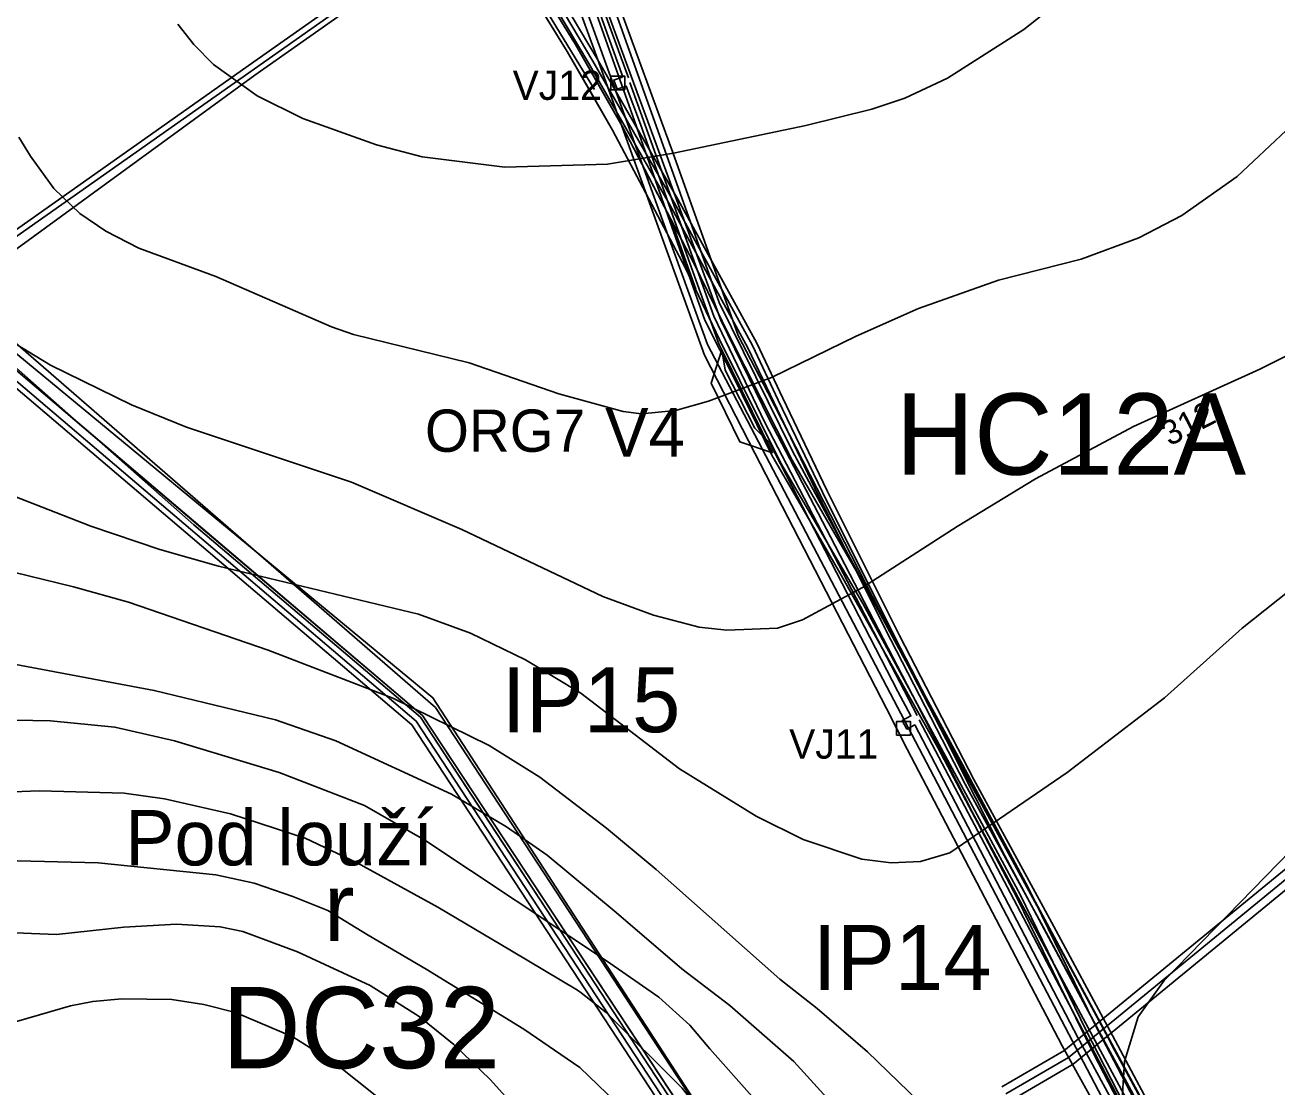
# Model space of a CAD drawing. Extents: x -1900516 to -575031, y -3809306 to -1157387.
# Drawn here: x -577737.9 to -577352.9, y -1159075.4 to -1158748.8 of the extents above; entities that cross this region are included whole.
import ezdxf

# ---------------------------------------------------------------- set-up
doc = ezdxf.new("R2010")
doc.units = 0
for name, color, linetype in [('01_MÍSTNÍ_NÁZVY', 7, 'Continuous'), ('01_PARCELY_NÁVRH_PC', 7, 'Continuous'), ('01_PARCELY_NÁVRH_ŽP', 7, 'Continuous'), ('01_PRVKY PRŮZKUMU', 7, 'Continuous'), ('01_PRVKY PSZ', 7, 'Continuous'), ('01_VRSTEVNICE', 7, 'Continuous'), ('02_KULTURY STAV', 7, 'Continuous'), ('03_PC_NÁVRH', 7, 'Continuous'), ('03_PC_OBJEKTY_NÁVRH', 7, 'Continuous'), ('03_PC_POPIS_NÁVRH', 7, 'Continuous'), ('04_ZPF_OP_ORGAN', 7, 'Continuous'), ('06_REVITALIZACE', 7, 'Continuous'), ('06_ÚSES_IP', 7, 'Continuous'), ('07_OCH_P A POPISY TI', 7, 'Continuous'), ('07_SDĚLOVACÍ', 7, 'Continuous'), ('07_VODOVOD', 7, 'Continuous')]:
    doc.layers.add(name, color=color, linetype=linetype)

msp = doc.modelspace()

# ---------------------------------------------------------------- linework, layer by layer
at = {"layer": '01_PARCELY_NÁVRH_PC'}
for points in [[(-577351.76, -1159160.35), (-577354.61, -1159155.38), (-577356.51, -1159151.86), (-577356.86, -1159151.18), (-577370.68, -1159126.55), (-577389.27, -1159092.33), (-577397.73, -1159076.44), (-577408.74, -1159056.24), (-577436.58, -1159004.27), (-577445.6, -1158986.42), (-577454.65, -1158968.56), (-577470.2, -1158938.32), (-577472.99, -1158933.04), (-577509.53, -1158861.87), (-577518.63, -1158844.3), (-577538.75, -1158787.99), (-577582.32, -1158668.78)], [(-577583.17, -1158700.75), (-577669.28, -1158761.41), (-577757.08, -1158823.28), (-577761.2, -1158827.86), (-577763.11, -1158834.28), (-577761.87, -1158840.85), (-577758.1, -1158845.78), (-577618.94, -1158964.02), (-577533.99, -1159093.64), (-577453.13, -1159217.05), (-577454.97, -1159225.17), (-577441.7, -1159217.16), (-577450.13, -1159215.24), (-577531.07, -1159091.72), (-577573.66, -1159026.72), (-577616.28, -1158961.68), (-577685.96, -1158902.49), (-577754.76, -1158841.86), (-577757.35, -1158838.39), (-577757.96, -1158834.51), (-577756.72, -1158830.19), (-577754.11, -1158827.49), (-577667.26, -1158764.27), (-577581.95, -1158704.17)], [(-577575.02, -1158706.36), (-577558.49, -1158752.55), (-577554.03, -1158764.77), (-577556.85, -1158765.79), (-577555.84, -1158768.61), (-577553.01, -1158767.59), (-577548.69, -1158779.36), (-577538.23, -1158808.96), (-577524.51, -1158846.88), (-577523.62, -1158848.73), (-577522.65, -1158854.98), (-577513.5, -1158872.76), (-577508.98, -1158877.19), (-577469.52, -1158953.79), (-577465.49, -1158961.25), (-577468.14, -1158962.67), (-577466.73, -1158965.31), (-577464.31, -1158964.03), (-577414.11, -1159060.16), (-577394.03, -1159097.19)]]:
    msp.add_lwpolyline(points, dxfattribs=at)
at = {"layer": '01_PARCELY_NÁVRH_ŽP'}
for points in [[(-577581.95, -1158704.17), (-577561.09, -1158761.47), (-577528.93, -1158850.38), (-577513.46, -1158880.5), (-577472.95, -1158959.01), (-577466.62, -1158971.48), (-577418.97, -1159062.74), (-577380.99, -1159131.08)], [(-577394.03, -1159097.19), (-577414.11, -1159060.16), (-577464.31, -1158964.02), (-577466.73, -1158965.31), (-577468.14, -1158962.67), (-577465.49, -1158961.25), (-577469.52, -1158953.79), (-577508.98, -1158877.19), (-577513.5, -1158872.76), (-577522.65, -1158854.98), (-577523.62, -1158848.73), (-577524.51, -1158846.88), (-577538.23, -1158808.96), (-577548.69, -1158779.36), (-577553.01, -1158767.59), (-577555.84, -1158768.61), (-577556.85, -1158765.79), (-577554.03, -1158764.77), (-577558.49, -1158752.55), (-577575.02, -1158706.36)]]:
    msp.add_lwpolyline(points, dxfattribs=at)
msp.add_lwpolyline([(-577611.67, -1158958.68), (-577751.04, -1158837.81), (-577757.34, -1158832.35), (-577757.96, -1158834.51), (-577757.35, -1158838.39), (-577754.76, -1158841.86), (-577685.96, -1158902.49), (-577616.28, -1158961.68), (-577594.97, -1158994.2), (-577573.66, -1159026.72), (-577531.07, -1159091.72), (-577450.13, -1159215.24), (-577441.7, -1159217.16), (-577445.54, -1159212.21)], close=True, dxfattribs=at)
at = {"layer": '01_PRVKY PRŮZKUMU'}
for p, q in [((-577571.21, -1158756.93), (-577582.84, -1158738.08)), ((-577580.08, -1158736.23), (-577568.65, -1158754.78)), ((-577568.65, -1158754.78), (-577561.45, -1158767.37)), ((-577564.26, -1158769.02), (-577571.21, -1158756.93)), ((-577557.3, -1158781.12), (-577564.26, -1158769.02)), ((-577561.45, -1158767.37), (-577554.25, -1158779.96)), ((-577546.08, -1158802.24), (-577557.3, -1158781.12)), ((-577554.25, -1158779.96), (-577543.28, -1158800.93)), ((-577543.28, -1158800.93), (-577539.28, -1158808.57)), ((-577534.87, -1158823.35), (-577546.08, -1158802.24)), ((-577531.67, -1158830.04), (-577539.28, -1158808.57)), ((-577531.67, -1158830.04), (-577534.87, -1158823.35))]:
    msp.add_line(p, q, dxfattribs=at)
at = {"layer": '01_PRVKY PSZ'}
for points in [[(-577557.73, -1158768.76), (-577553.51, -1158768.76), (-577553.51, -1158764.54), (-577557.73, -1158764.54)], [(-577469.87, -1158967.17), (-577465.64, -1158967.17), (-577465.64, -1158962.95), (-577469.87, -1158962.95)]]:
    msp.add_lwpolyline(points, close=True, dxfattribs=at)
at = {"layer": '01_VRSTEVNICE'}
for points in [[(-577159.9, -1158732.48), (-577156.09, -1158754.21), (-577154.68, -1158768.04), (-577153.97, -1158786.38), (-577154.25, -1158797.1), (-577155.38, -1158806.42), (-577158.34, -1158818.83), (-577164.84, -1158836.89), (-577172.74, -1158851), (-577180.36, -1158861.02), (-577185.15, -1158866.1), (-577204.77, -1158882.89), (-577248.65, -1158912.24), (-577284.34, -1158940.88), (-577302.68, -1158957.24), (-577329.21, -1158982.64), (-577387.62, -1159042.6), (-577395.61, -1159053.76)], [(-577413.72, -1158736.72), (-577430.8, -1158750.26), (-577454.22, -1158765.22), (-577467.34, -1158771.28), (-577477.5, -1158774.67), (-577497.81, -1158779.75), (-577538.45, -1158788.21), (-577558.77, -1158791.6), (-577590.37, -1158792.59), (-577615.77, -1158789.34), (-577629.88, -1158785.67), (-577652.45, -1158777.63), (-577666.56, -1158770.58), (-577679.96, -1158760.98), (-577686.03, -1158754.78), (-577690.97, -1158748.57)], [(-577350.09, -1158781.3), (-577365.19, -1158795.41), (-577382.12, -1158807.4), (-577395.38, -1158814.32), (-577413.16, -1158820.81), (-577438.56, -1158827.3), (-577463.11, -1158836.04), (-577482.29, -1158844.51), (-577508.4, -1158857.21), (-577527.73, -1158864.54), (-577537.89, -1158867.37), (-577548.33, -1158868.35), (-577553.97, -1158867.65), (-577573.72, -1158862.29), (-577601.38, -1158852.69), (-577636.93, -1158843.95), (-577643.7, -1158841.69), (-577679.26, -1158826.17), (-577702.96, -1158817.42), (-577713.12, -1158812.2), (-577721.02, -1158806.84), (-577729.07, -1158799.08), (-577736.26, -1158789.2), (-577739.79, -1158783.28)], [(-577333.86, -1158842.53), (-577358.13, -1158854.67), (-577397.07, -1158872.3), (-577427.13, -1158888.39), (-577451.25, -1158903.06), (-577480.32, -1158921.83), (-577498.8, -1158931.71), (-577506.56, -1158934.25), (-577522.08, -1158934.95), (-577530.55, -1158933.96), (-577544.66, -1158930.29), (-577560.18, -1158924.51), (-577603.63, -1158903.91), (-577637.5, -1158889.38), (-577688.29, -1158872.45), (-577705.22, -1158865.67), (-577730.05, -1158853.4), (-577754.04, -1158838.87)], [(-577345.72, -1158920), (-577363.64, -1158934.25), (-577387.48, -1158955.69), (-577417.39, -1158978.69), (-577453.51, -1159003.38), (-577462.54, -1159006.06), (-577471.57, -1159006.49), (-577480.6, -1159005.36), (-577498.66, -1158999.29), (-577513.05, -1158992.09), (-577536.61, -1158977.56), (-577566.95, -1158954.28), (-577584.02, -1158943.98), (-577600.95, -1158935.8), (-577616.9, -1158930.01), (-577678.41, -1158915.2), (-577696.47, -1158910.12), (-577717.64, -1158902.92), (-577754.32, -1158888.67)], [(-577755.45, -1158913.65), (-577723, -1158921.55), (-577706.07, -1158926.34), (-577663.18, -1158941.02), (-577624.8, -1158955.83), (-577595.17, -1158970.36), (-577579.65, -1158980.1), (-577559.05, -1158995.76), (-577543.81, -1159008.46), (-577505.83, -1159042.26)], [(-577755.45, -1158913.65), (-577723, -1158921.55), (-577706.07, -1158926.34), (-577663.18, -1158941.02), (-577624.8, -1158955.83), (-577595.17, -1158970.36), (-577579.65, -1158980.1), (-577559.05, -1158995.76), (-577543.81, -1159008.46), (-577505.83, -1159042.26)], [(-577773.51, -1158939.32), (-577698.17, -1158953.43), (-577660.92, -1158962.46), (-577642.29, -1158968.95), (-577606.74, -1158985.32), (-577589.81, -1158995.34), (-577577.39, -1159004.09), (-577556.08, -1159021.72), (-577535.9, -1159039.02)], [(-577773.51, -1158939.32), (-577698.17, -1158953.43), (-577660.92, -1158962.46), (-577642.29, -1158968.95), (-577606.74, -1158985.32), (-577589.81, -1158995.34), (-577577.39, -1159004.09), (-577556.08, -1159021.72), (-577535.9, -1159039.02)], [(-577768.15, -1158962.04), (-577730.05, -1158962.75), (-577710.3, -1158964.72), (-577691.96, -1158968.95), (-577659.79, -1158978.69), (-577633.55, -1158988.85), (-577614.92, -1158999.43), (-577559.15, -1159036.54)], [(-577768.15, -1158962.04), (-577730.05, -1158962.75), (-577710.3, -1158964.72), (-577691.96, -1158968.95), (-577659.79, -1158978.69), (-577633.55, -1158988.85), (-577614.92, -1158999.43), (-577559.15, -1159036.54)], [(-577632.38, -1159028.65), (-577644.83, -1159021.08), (-577655.56, -1159016.78), (-577667.41, -1159012.69), (-577679.26, -1159010.15), (-577715.38, -1159006.49), (-577761.09, -1159005.36), (-577821.76, -1158998.87), (-577833.61, -1158994.77), (-577852.24, -1158983.2), (-577856.33, -1158982.92), (-577860.04, -1158983.83), (-577862.96, -1158986.87), (-577870.3, -1158996.04), (-577875.01, -1159003.03)], [(-577752.63, -1158985.04), (-577733.44, -1158984.33), (-577707.48, -1158985.04), (-577695.06, -1158986.73), (-577674.74, -1158991.39), (-577651.75, -1158998.86), (-577635.8, -1159006.48), (-577610.97, -1159020.03), (-577588.27, -1159033.46)], [(-577752.63, -1158985.04), (-577733.44, -1158984.33), (-577707.48, -1158985.04), (-577695.06, -1158986.73), (-577674.74, -1158991.39), (-577651.75, -1158998.86), (-577635.8, -1159006.48), (-577610.97, -1159020.03), (-577588.27, -1159033.46)], [(-577528.87, -1159360.3), (-577549.85, -1159284.52), (-577556.84, -1159251.8), (-577559.63, -1159235.02), (-577560.61, -1159218.25), (-577558.52, -1159164.55), (-577559.07, -1159150.57), (-577561.59, -1159133.79), (-577565.51, -1159118.41), (-577569.98, -1159106.39), (-577574.87, -1159097.44), (-577583.68, -1159085.42), (-577594.87, -1159073.11), (-577606.05, -1159062.35), (-577616.68, -1159053.68), (-577631.78, -1159044.17), (-577654.15, -1159033.82), (-577670.93, -1159027.53), (-577677.92, -1159026.13), (-577691.34, -1159025.29), (-577707.56, -1159026.27), (-577728.26, -1159028.51), (-577746.16, -1159027.81)], [(-577632.38, -1159028.65), (-577614.58, -1159039.14), (-577584.52, -1159057.59), (-577567.32, -1159069.34), (-577556.14, -1159080.1), (-577548.45, -1159089.05), (-577541.46, -1159098.7), (-577535.1, -1159108.52), (-577532.65, -1159114.5), (-577528.73, -1159127.64), (-577526.64, -1159141.06), (-577526.64, -1159153.65), (-577528.03, -1159170.43), (-577537.12, -1159216.57), (-577537.78, -1159230.12), (-577536.98, -1159237.54), (-577531.95, -1159266.9), (-577523.28, -1159292.07), (-577506.36, -1159334.02), (-577493.5, -1159373.17)], [(-577588.27, -1159033.46), (-577568.02, -1159045.57), (-577566.91, -1159046.41), (-577559.21, -1159052.42), (-577535.86, -1159075.77), (-577526.78, -1159087.23), (-577515.45, -1159105.83), (-577506.22, -1159127.92), (-577502.59, -1159143.02), (-577501.61, -1159159.8), (-577504.96, -1159191.68), (-577505.61, -1159217.18), (-577505.1, -1159233.35), (-577503.7, -1159252.64), (-577502.03, -1159262.71), (-577497.69, -1159279.49), (-577488.74, -1159301.3), (-577455.47, -1159363.38)], [(-577513.49, -1159079.26), (-577527.33, -1159063.6), (-577533.52, -1159056.37), (-577542.99, -1159047.8), (-577559.15, -1159036.54)], [(-577535.9, -1159039.02), (-577521.14, -1159050.35), (-577501.47, -1159067.52), (-577481.89, -1159089.05)], [(-577505.83, -1159042.26), (-577494.34, -1159051.2), (-577478.82, -1159064.58), (-577450.43, -1159091.99), (-577436.31, -1159104.43), (-577425.96, -1159111), (-577420.09, -1159112.26), (-577415.96, -1159112.31), (-577412.96, -1159111.56), (-577411, -1159110.58), (-577406.66, -1159107.26), (-577404.71, -1159104.71), (-577401.78, -1159099.12), (-577399.82, -1159067.52), (-577395.61, -1159053.76)], [(-577746.99, -1159057.03), (-577723.92, -1159050.46), (-577717.07, -1159049.06), (-577708.12, -1159048.22), (-577692.74, -1159048.5), (-577682.96, -1159050.04), (-577673.17, -1159052.42), (-577655.55, -1159059.97), (-577641.85, -1159068.64), (-577629.68, -1159078.28), (-577614.72, -1159093.25), (-577604.66, -1159106.11), (-577595.99, -1159121.77), (-577592.35, -1159133.52), (-577590.67, -1159147.22), (-577590.26, -1159166.79), (-577590.67, -1159196.99), (-577589, -1159217.13), (-577584.8, -1159235.02), (-577575.85, -1159264.11), (-577564.95, -1159304.38), (-577557.12, -1159340.17)]]:
    msp.add_lwpolyline(points, dxfattribs=at)
at = {"layer": '02_KULTURY STAV'}
for points in [[(-577594.48, -1158719.22), (-577571.21, -1158756.93), (-577557.3, -1158781.12), (-577534.87, -1158823.35), (-577524.3, -1158845.5), (-577505.5, -1158883.53), (-577480.29, -1158926.68), (-577452.77, -1158977.4), (-577431.83, -1159016.39), (-577411.67, -1159057.8), (-577388.29, -1159103.32), (-577365.57, -1159143.24), (-577356.66, -1159160.73), (-577357.02, -1159165.97), (-577359.5, -1159169.84), (-577371.82, -1159178.25), (-577420.8, -1159207.62), (-577527.72, -1159271.03), (-577597.7, -1159313.36), (-577671.8, -1159358.28)], [(-577671.8, -1159358.28), (-577597.7, -1159313.36), (-577527.72, -1159271.03), (-577420.8, -1159207.62), (-577371.82, -1159178.25), (-577359.5, -1159169.84), (-577357.02, -1159165.97), (-577356.66, -1159160.73), (-577365.57, -1159143.24), (-577388.29, -1159103.32), (-577411.67, -1159057.8), (-577431.83, -1159016.39), (-577452.77, -1158977.4), (-577480.29, -1158926.68), (-577505.5, -1158883.53), (-577524.3, -1158845.5), (-577534.87, -1158823.35), (-577557.3, -1158781.12), (-577571.21, -1158756.93), (-577594.48, -1158719.22)], [(-577671.8, -1159358.28), (-577597.7, -1159313.36), (-577527.72, -1159271.03), (-577420.8, -1159207.62), (-577371.82, -1159178.25), (-577359.5, -1159169.84), (-577357.02, -1159165.97), (-577356.66, -1159160.73), (-577365.57, -1159143.24), (-577388.29, -1159103.32), (-577411.67, -1159057.8), (-577431.83, -1159016.39), (-577452.77, -1158977.4), (-577480.29, -1158926.68), (-577505.5, -1158883.53), (-577524.3, -1158845.5), (-577534.87, -1158823.35), (-577557.3, -1158781.12), (-577571.21, -1158756.93), (-577594.48, -1158719.22)], [(-577343.83, -1159175.09), (-577362.95, -1159141.11), (-577382.07, -1159107.13), (-577384.94, -1159101.94), (-577409.06, -1159055.82), (-577429.3, -1159014.25), (-577449.6, -1158976.26), (-577478.22, -1158923.74), (-577502.03, -1158882.67), (-577521.42, -1158844.35), (-577532.3, -1158821.9), (-577554.25, -1158779.96), (-577568.65, -1158754.78), (-577591.51, -1158717.68)], [(-577591.51, -1158717.68), (-577568.65, -1158754.78), (-577554.25, -1158779.96), (-577532.3, -1158821.9), (-577521.42, -1158844.35), (-577502.03, -1158882.67), (-577478.22, -1158923.74), (-577449.6, -1158976.26), (-577429.3, -1159014.25), (-577409.06, -1159055.82), (-577384.94, -1159101.94), (-577382.07, -1159107.13), (-577362.95, -1159141.11), (-577343.83, -1159175.09)], [(-577591.51, -1158717.68), (-577568.65, -1158754.78), (-577554.25, -1158779.96), (-577532.3, -1158821.9), (-577521.42, -1158844.35), (-577502.03, -1158882.67), (-577478.22, -1158923.74), (-577449.6, -1158976.26), (-577429.3, -1159014.25), (-577409.06, -1159055.82), (-577384.94, -1159101.94), (-577382.07, -1159107.13), (-577362.95, -1159141.11), (-577343.83, -1159175.09)]]:
    msp.add_lwpolyline(points, dxfattribs=at)
at = {"layer": '03_PC_NÁVRH'}
for points in [[(-577616.77, -1158582.27), (-577571.41, -1158710.34), (-577523.9, -1158839.56), (-577508.98, -1158870.19), (-577490.25, -1158906.16), (-577463.66, -1158957.42), (-577446.67, -1158990.72), (-577387.31, -1159101.23), (-577375.8, -1159121.6), (-577366.66, -1159137.78), (-577359.5, -1159150.86), (-577353.72, -1159161.89), (-577350.84, -1159167.41)], [(-577577.98, -1158699.23), (-577758.56, -1158826.46), (-577761.69, -1158835.41), (-577756.57, -1158844.78), (-577617.61, -1158962.85), (-577447.45, -1159222.52)]]:
    msp.add_lwpolyline(points, dxfattribs=at)
at = {"layer": '03_PC_OBJEKTY_NÁVRH'}
msp.add_line((-577618.07, -1158583.81), (-577552.37, -1158765.12), dxfattribs=at)
for points in [[(-577551.92, -1158766.55), (-577526.05, -1158838.41), (-577510.43, -1158871.07), (-577463.52, -1158961.18)], [(-577462.94, -1158962.5), (-577375.57, -1159128.2), (-577363.21, -1159152.94), (-577363.87, -1159154.67)]]:
    msp.add_lwpolyline(points, dxfattribs=at)
msp.add_lwpolyline([(-577508.08, -1158880.38), (-577518.12, -1158876.95), (-577526.93, -1158859), (-577523.62, -1158848.73)], close=True, dxfattribs=at)
at = {"layer": '04_ZPF_OP_ORGAN'}
msp.add_lwpolyline([(-577350.05, -1159164.2), (-576903.86, -1158894.73), (-577022.53, -1158810.48), (-577009.99, -1158786.2), (-576892.58, -1158838.93), (-576871.91, -1158799.96), (-577005.93, -1158719.17), (-577009.6, -1158721.31), (-577178.26, -1158431.99), (-577189.42, -1158416.79), (-577219.92, -1158422.77), (-577242.89, -1158431.88), (-577294.41, -1158455.68), (-577323.82, -1158465.16), (-577429.53, -1158496.15), (-577519.46, -1158523.89), (-577547.21, -1158534.99), (-577564.81, -1158545.04), (-577613.08, -1158585.53), (-577524.43, -1158834.12), (-577501.85, -1158879.88), (-577349.53, -1159162.53)], close=True, dxfattribs=at)
msp.add_lwpolyline([(-577350.05, -1159164.2), (-576903.86, -1158894.73), (-577022.53, -1158810.48), (-577009.99, -1158786.2), (-576892.58, -1158838.93), (-576871.91, -1158799.96), (-577005.93, -1158719.17), (-577009.6, -1158721.31), (-577178.26, -1158431.99), (-577189.42, -1158416.79), (-577219.92, -1158422.77), (-577242.89, -1158431.88), (-577294.41, -1158455.68), (-577323.82, -1158465.16), (-577429.53, -1158496.15), (-577519.46, -1158523.89), (-577547.21, -1158534.99), (-577564.81, -1158545.04), (-577613.08, -1158585.53), (-577524.43, -1158834.12), (-577501.85, -1158879.88), (-577349.53, -1159162.53)], close=True, dxfattribs=at)
for points in [[(-577400.24, -1159082.66), (-577409.3, -1159065.06), (-577420.2, -1159043.16), (-577424.86, -1159033.64), (-577428.81, -1159025.48), (-577432.76, -1159017.31), (-577444.94, -1158994.27), (-577457.12, -1158971.22), (-577472.21, -1158944.24), (-577487.3, -1158917.25), (-577497.77, -1158899.17), (-577508.24, -1158881.09), (-577519.67, -1158857.85), (-577528.82, -1158839.57), (-577540.23, -1158807.36), (-577551.64, -1158775.15), (-577584.85, -1158681.55)], [(-577400.24, -1159082.66), (-577409.3, -1159065.06), (-577420.2, -1159043.16), (-577424.86, -1159033.64), (-577428.81, -1159025.48), (-577432.76, -1159017.31), (-577444.94, -1158994.27), (-577457.12, -1158971.22), (-577472.21, -1158944.24), (-577487.3, -1158917.25), (-577497.77, -1158899.17), (-577508.24, -1158881.09), (-577519.67, -1158857.85), (-577528.82, -1158839.57), (-577540.23, -1158807.36), (-577551.64, -1158775.15), (-577584.85, -1158681.55)], [(-577770.71, -1158834.12), (-577754.6, -1158843.17), (-577685.16, -1158902.18), (-577615.72, -1158961.18)], [(-577734.71, -1159397.93), (-577567.46, -1159295.07), (-577445.15, -1159219.7), (-577615.72, -1158961.18), (-577754.6, -1158843.17)], [(-577754.6, -1158843.17), (-577685.16, -1158902.18), (-577615.72, -1158961.18), (-577530.44, -1159090.44)], [(-577530.44, -1159090.44), (-577615.72, -1158961.18), (-577685.16, -1158902.18), (-577754.6, -1158843.17)], [(-577615.72, -1158961.18), (-577530.44, -1159090.44), (-577445.15, -1159219.7)]]:
    msp.add_lwpolyline(points, dxfattribs=at)
at = {"layer": '06_REVITALIZACE'}
msp.add_lwpolyline([(-577672.14, -1158602.04), (-577633.03, -1158653.59), (-577562.79, -1158768.7)], dxfattribs=at)
at = {"layer": '06_ÚSES_IP'}
for points in [[(-577364.12, -1159159.87), (-577528.06, -1158847.05), (-577621.02, -1158590.12)], [(-577754.99, -1158838.04), (-577612.49, -1158955.71), (-577442.13, -1159217.87)]]:
    msp.add_lwpolyline(points, dxfattribs=at)
at = {"layer": '07_OCH_P A POPISY TI'}
for points in [[(-576191.25, -1158057.87), (-577418.49, -1159064.24), (-577437.53, -1159075.36)], [(-576188.08, -1158061.74), (-577415.62, -1159068.35), (-577435.01, -1159079.68)], [(-577403.53, -1159059.54), (-577422.21, -1159024.68), (-577446.18, -1158980.81), (-577468.98, -1158936.56), (-577491.37, -1158891.86), (-577504.92, -1158863.55), (-577512.91, -1158846.71), (-577537.04, -1158802.64), (-577561.96, -1158759.2), (-577587.55, -1158716.13)], [(-577406.17, -1159060.96), (-577424.85, -1159026.11), (-577448.83, -1158982.22), (-577471.66, -1158937.92), (-577494.07, -1158893.18), (-577507.63, -1158864.84), (-577515.59, -1158848.07), (-577539.65, -1158804.1), (-577564.55, -1158760.71), (-577590.12, -1158717.67)], [(-577394.7, -1159082.28), (-577401.23, -1159070.17), (-577406.17, -1159060.96)], [(-577392.06, -1159080.86), (-577398.59, -1159068.75), (-577403.53, -1159059.54)]]:
    msp.add_lwpolyline(points, dxfattribs=at)
at = {"layer": '07_SDĚLOVACÍ'}
msp.add_lwpolyline([(-577386.85, -1159093.67), (-577399.91, -1159069.46), (-577403.44, -1159062.89), (-577404.85, -1159060.25), (-577423.53, -1159025.39), (-577447.51, -1158981.52), (-577470.32, -1158937.24), (-577492.72, -1158892.52), (-577506.28, -1158864.2), (-577514.25, -1158847.39), (-577538.34, -1158803.37), (-577563.26, -1158759.96), (-577588.83, -1158716.9)], dxfattribs=at)
at = {"layer": '07_VODOVOD'}
msp.add_lwpolyline([(-576189.67, -1158059.8), (-577417.05, -1159066.3), (-577436.27, -1159077.52)], dxfattribs=at)

# ---------------------------------------------------------------- texts
at = {"layer": '01_MÍSTNÍ_NÁZVY'}
msp.add_text('Pod louží', height=17, dxfattribs=at).set_placement((-577707.12, -1159007.23))
at = {"layer": '01_PRVKY PSZ'}
for s, p in [('VJ12', (-577587.96, -1158771.85)), ('VJ11', (-577502.93, -1158974.4))]:
    msp.add_text(s, height=9, dxfattribs=at).set_placement(p)
at = {"layer": '01_VRSTEVNICE'}
msp.add_text('312', height=7.5, rotation=27.3281, dxfattribs=at).set_placement((-577385.96, -1158878.46))
at = {"layer": '02_KULTURY STAV'}
msp.add_text('r', height=21, dxfattribs=at).set_placement((-577645.97, -1159030.48))
at = {"layer": '03_PC_OBJEKTY_NÁVRH'}
msp.add_text('V4', height=15, dxfattribs=at).set_placement((-577559.53, -1158881.59))
at = {"layer": '03_PC_POPIS_NÁVRH'}
for s, p in [('HC12A', (-577470.17, -1158887.1)), ('DC32', (-577677.31, -1159069.6))]:
    msp.add_text(s, height=25, dxfattribs=at).set_placement(p)
at = {"layer": '04_ZPF_OP_ORGAN'}
msp.add_text('ORG7', height=13, dxfattribs=at).set_placement((-577614.93, -1158880.07))
at = {"layer": '06_ÚSES_IP'}
for s, p in [('IP15', (-577591.37, -1158966.29)), ('IP14', (-577495.69, -1159045.56))]:
    msp.add_text(s, height=20, dxfattribs=at).set_placement(p)

doc.saveas('drawing.dxf')
